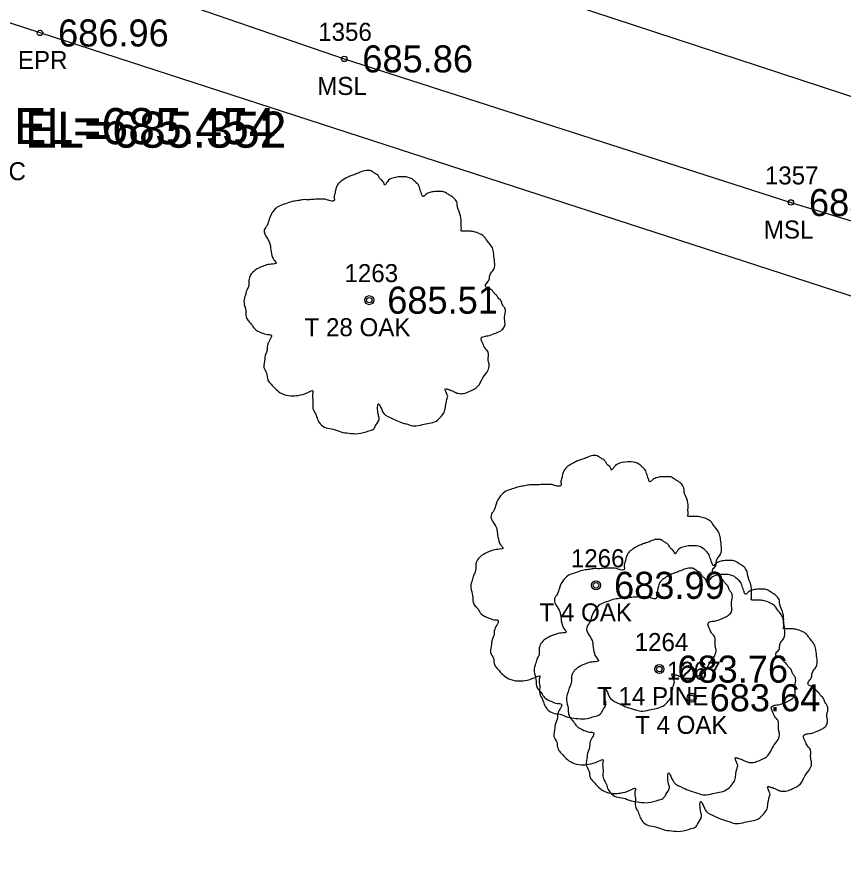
# Model space of a CAD drawing. Extents: x 1655137 to 1657928, y 1003994 to 1005407.
# Drawn here: x 1655939.35 to 1655985.18, y 1004711.37 to 1004758.76 of the extents above; entities that cross this region are included whole.
import ezdxf

# ---------------------------------------------------------------- set-up
doc = ezdxf.new("R2010")
doc.units = 0
for name, color, linetype in [('RD_EX_DR_Pipe_txCode', 7, 'Continuous'), ('RD_EX_Misc', 7, 'Continuous'), ('RD_EX_Misc_txCode', 7, 'Continuous'), ('RD_EX_Road', 7, 'Continuous'), ('RD_EX_Road_txCode', 7, 'Continuous'), ('RD_EX_TX_Misc_ELEV', 7, 'Continuous'), ('RD_EX_TX_Road_ELEV', 7, 'Continuous'), ('RD_EX_TX_VEG_ELEV', 7, 'Continuous'), ('RD_EX_VEG', 7, 'Continuous'), ('RD_EX_VEG_txCode', 7, 'Continuous'), ('RD_HC_Cl', 7, 'Continuous'), ('RD_SMD_Locator', 7, 'Continuous'), ('RD_TX_Pipe_ElevEX', 7, 'Continuous')]:
    doc.layers.add(name, color=color, linetype=linetype)

msp = doc.modelspace()

# ---------------------------------------------------------------- linework, layer by layer
at = {"layer": 'RD_EX_Misc'}
msp.add_lwpolyline([(1655875.572, 1004783.81), (1655899.124, 1004775.727), (1655924.143, 1004767.915), (1655957.486, 1004756.441), (1655982.243, 1004748.48), (1656011.779, 1004739.501), (1656033.158, 1004732.174), (1656057.837, 1004724.625), (1656091.047, 1004714.315), (1656106.296, 1004710.837), (1656119.065, 1004707.85), (1656127.527, 1004711.026), (1656137.413, 1004709.544), (1656150.275, 1004705.031), (1656164.334, 1004699.598), (1656171.578, 1004694.85), (1656180.966, 1004693.871), (1656197.975, 1004688.492), (1656215.111, 1004682.576), (1656240.683, 1004675.392), (1656271.878, 1004665.005), (1656304.44, 1004655.084)], dxfattribs=at)
at = {"layer": 'RD_EX_Road'}
msp.add_lwpolyline([(1656358.504, 1004619.827), (1656328.784, 1004629.475), (1656280.774, 1004645.393), (1656247.663, 1004656.111), (1656244.505, 1004656.516), (1656222.03, 1004663.569), (1656217.647, 1004665.963), (1656183.416, 1004677.324), (1656134.594, 1004693.716), (1656086.193, 1004709.749), (1656037.581, 1004726.126), (1655989.575, 1004741.988), (1655940.618, 1004757.879), (1655892.373, 1004773.61), (1655843.478, 1004789.356), (1655805.734, 1004801.404), (1655779.222, 1004810.434), (1655768.796, 1004813.103), (1655744.595, 1004822.13), (1655698.832, 1004837.654)], dxfattribs=at)
at = {"layer": 'RD_EX_VEG'}
for centre, radius in [((1655958.865, 1004743.064), 0.25), ((1655958.853, 1004743.046), 0.0001), ((1655971.438, 1004727.254), 0.25), ((1655971.425, 1004727.235), 0.0001), ((1655974.95, 1004722.609), 0.25), ((1655974.937, 1004722.59), 0.0001), ((1655976.737, 1004721.018), 0.25), ((1655976.724, 1004720.999), 0.0001)]:
    msp.add_circle(centre, radius, dxfattribs=at)
for points in [[(1655958.997, 1004750.232), (1655958.697, 1004750.257), (1655958.372, 1004750.157), (1655958.122, 1004750.057), (1655957.898, 1004749.982), (1655957.673, 1004749.882), (1655957.373, 1004749.707), (1655957.148, 1004749.507), (1655957.023, 1004749.257), (1655956.973, 1004749.032), (1655956.923, 1004748.757), (1655956.923, 1004748.582), (1655956.798, 1004748.557), (1655956.648, 1004748.582), (1655956.398, 1004748.657), (1655956.148, 1004748.657), (1655955.898, 1004748.657), (1655955.549, 1004748.632), (1655955.199, 1004748.632), (1655954.924, 1004748.582), (1655954.599, 1004748.532), (1655954.224, 1004748.407), (1655953.874, 1004748.282), (1655953.574, 1004748.033), (1655953.325, 1004747.558), (1655953.2, 1004747.208), (1655953.05, 1004746.958), (1655953.2, 1004746.508), (1655953.375, 1004746.158), (1655953.399, 1004745.958), (1655953.474, 1004745.534), (1655953.574, 1004745.309), (1655953.699, 1004745.109), (1655953.624, 1004745.084), (1655953.25, 1004745.034), (1655952.95, 1004744.934), (1655952.525, 1004744.709), (1655952.3, 1004744.484), (1655952.2, 1004744.159), (1655952.175, 1004743.809), (1655952.075, 1004743.61), (1655952, 1004743.335), (1655951.975, 1004743.26), (1655951.925, 1004742.935), (1655952.025, 1004742.485), (1655952.05, 1004742.135), (1655952.175, 1004741.91), (1655952.325, 1004741.735), (1655952.5, 1004741.485), (1655952.9, 1004741.261), (1655953.225, 1004741.161), (1655953.424, 1004741.136), (1655953.25, 1004740.636), (1655953.2, 1004740.286), (1655953.075, 1004739.886), (1655953.075, 1004739.811), (1655953.025, 1004739.336), (1655953.175, 1004739.011), (1655953.25, 1004738.637), (1655953.424, 1004738.412), (1655953.699, 1004738.112), (1655954.024, 1004737.887), (1655954.524, 1004737.762), (1655954.924, 1004737.787), (1655955.499, 1004737.962), (1655955.748, 1004738.037), (1655955.723, 1004737.862), (1655955.748, 1004737.487), (1655955.748, 1004737.062), (1655955.898, 1004736.738), (1655955.998, 1004736.463), (1655956.148, 1004736.213), (1655956.473, 1004735.988), (1655956.873, 1004735.913), (1655957.298, 1004735.763), (1655957.748, 1004735.688), (1655958.247, 1004735.663), (1655958.847, 1004735.813), (1655959.122, 1004735.938), (1655959.222, 1004736.113), (1655959.422, 1004736.488), (1655959.372, 1004736.713), (1655959.397, 1004737.312), (1655959.497, 1004737.137), (1655959.672, 1004736.787), (1655960.172, 1004736.488), (1655960.571, 1004736.313), (1655961.046, 1004736.163), (1655961.346, 1004736.088), (1655961.821, 1004736.163), (1655962.196, 1004736.238), (1655962.57, 1004736.363), (1655962.87, 1004736.638), (1655963.045, 1004736.912), (1655963.095, 1004737.187), (1655963.17, 1004737.562), (1655963.22, 1004737.737)], [(1655963.22, 1004737.737), (1655963.145, 1004737.912), (1655963.095, 1004738.162), (1655963.17, 1004738.137), (1655963.345, 1004738.087), (1655963.62, 1004737.962), (1655963.845, 1004737.887), (1655964.17, 1004737.912), (1655964.445, 1004738.012), (1655964.894, 1004738.287), (1655965.169, 1004738.762), (1655965.444, 1004739.161), (1655965.519, 1004739.486), (1655965.469, 1004739.711), (1655965.444, 1004740.211), (1655965.244, 1004740.461), (1655965.194, 1004740.586), (1655965.094, 1004740.986), (1655965.169, 1004741.036), (1655965.444, 1004741.086), (1655965.819, 1004741.211), (1655966.094, 1004741.335), (1655966.319, 1004741.51), (1655966.394, 1004741.735), (1655966.369, 1004742.135), (1655966.419, 1004742.535), (1655966.344, 1004742.685), (1655966.244, 1004742.835), (1655966.169, 1004743.035), (1655966.019, 1004743.185), (1655965.919, 1004743.335), (1655965.819, 1004743.435), (1655965.694, 1004743.585), (1655965.519, 1004743.709), (1655965.369, 1004743.759), (1655965.319, 1004743.909), (1655965.469, 1004744.109), (1655965.519, 1004744.209), (1655965.544, 1004744.434), (1655965.769, 1004744.784), (1655965.819, 1004745.184), (1655965.769, 1004745.609), (1655965.719, 1004745.884), (1655965.569, 1004746.158), (1655965.369, 1004746.408), (1655965.244, 1004746.583), (1655965.069, 1004746.708), (1655964.745, 1004746.833), (1655964.495, 1004746.883), (1655964.145, 1004746.883), (1655963.945, 1004746.933), (1655963.97, 1004746.983), (1655963.97, 1004747.133), (1655963.97, 1004747.408), (1655963.895, 1004747.858), (1655963.745, 1004748.357), (1655963.745, 1004748.382), (1655963.645, 1004748.632), (1655963.42, 1004748.832), (1655963.245, 1004748.932), (1655963.045, 1004749.057), (1655962.795, 1004749.082), (1655962.496, 1004749.082), (1655962.221, 1004749.032), (1655962.021, 1004748.932), (1655961.846, 1004748.807), (1655961.771, 1004748.957), (1655961.671, 1004749.257), (1655961.621, 1004749.407), (1655961.471, 1004749.582), (1655961.246, 1004749.782), (1655960.796, 1004749.907), (1655960.172, 1004749.832), (1655959.872, 1004749.632), (1655959.722, 1004749.457), (1655959.672, 1004749.582), (1655959.472, 1004749.782), (1655959.372, 1004749.957), (1655959.197, 1004750.082), (1655959.047, 1004750.182), (1655958.947, 1004750.232)], [(1655971.57, 1004734.421), (1655971.27, 1004734.446), (1655970.945, 1004734.346), (1655970.695, 1004734.246), (1655970.47, 1004734.171), (1655970.245, 1004734.071), (1655969.945, 1004733.897), (1655969.721, 1004733.697), (1655969.596, 1004733.447), (1655969.546, 1004733.222), (1655969.496, 1004732.947), (1655969.496, 1004732.772), (1655969.371, 1004732.747), (1655969.221, 1004732.772), (1655968.971, 1004732.847), (1655968.721, 1004732.847), (1655968.471, 1004732.847), (1655968.121, 1004732.822), (1655967.771, 1004732.822), (1655967.497, 1004732.772), (1655967.172, 1004732.722), (1655966.797, 1004732.597), (1655966.447, 1004732.472), (1655966.147, 1004732.222), (1655965.897, 1004731.748), (1655965.772, 1004731.398), (1655965.622, 1004731.148), (1655965.772, 1004730.698), (1655965.947, 1004730.348), (1655965.972, 1004730.148), (1655966.047, 1004729.723), (1655966.147, 1004729.499), (1655966.272, 1004729.299), (1655966.197, 1004729.274), (1655965.822, 1004729.224), (1655965.522, 1004729.124), (1655965.098, 1004728.899), (1655964.873, 1004728.674), (1655964.773, 1004728.349), (1655964.748, 1004727.999), (1655964.648, 1004727.799), (1655964.573, 1004727.524), (1655964.548, 1004727.449), (1655964.498, 1004727.125), (1655964.598, 1004726.675), (1655964.623, 1004726.325), (1655964.748, 1004726.1), (1655964.898, 1004725.925), (1655965.073, 1004725.675), (1655965.472, 1004725.45), (1655965.797, 1004725.35), (1655965.997, 1004725.325), (1655965.822, 1004724.826), (1655965.772, 1004724.476), (1655965.647, 1004724.076), (1655965.647, 1004724.001), (1655965.597, 1004723.526), (1655965.747, 1004723.201), (1655965.822, 1004722.826), (1655965.997, 1004722.602), (1655966.272, 1004722.302), (1655966.597, 1004722.077), (1655967.097, 1004721.952), (1655967.497, 1004721.977), (1655968.071, 1004722.152), (1655968.321, 1004722.227), (1655968.296, 1004722.052), (1655968.321, 1004721.677), (1655968.321, 1004721.252), (1655968.471, 1004720.927), (1655968.571, 1004720.652), (1655968.721, 1004720.402), (1655969.046, 1004720.178), (1655969.446, 1004720.103), (1655969.87, 1004719.953), (1655970.32, 1004719.878), (1655970.82, 1004719.853), (1655971.42, 1004720.003), (1655971.695, 1004720.128), (1655971.795, 1004720.303), (1655971.995, 1004720.677), (1655971.945, 1004720.902), (1655971.97, 1004721.502), (1655972.069, 1004721.327), (1655972.244, 1004720.977), (1655972.744, 1004720.677), (1655973.144, 1004720.502), (1655973.619, 1004720.352), (1655973.919, 1004720.278), (1655974.393, 1004720.352), (1655974.768, 1004720.427), (1655975.143, 1004720.552), (1655975.443, 1004720.827), (1655975.618, 1004721.102), (1655975.668, 1004721.377), (1655975.743, 1004721.752), (1655975.793, 1004721.927)], [(1655975.793, 1004721.927), (1655975.718, 1004722.102), (1655975.668, 1004722.352), (1655975.743, 1004722.327), (1655975.918, 1004722.277), (1655976.193, 1004722.152), (1655976.418, 1004722.077), (1655976.742, 1004722.102), (1655977.017, 1004722.202), (1655977.467, 1004722.477), (1655977.742, 1004722.951), (1655978.017, 1004723.351), (1655978.092, 1004723.676), (1655978.042, 1004723.901), (1655978.017, 1004724.401), (1655977.817, 1004724.651), (1655977.767, 1004724.776), (1655977.667, 1004725.175), (1655977.742, 1004725.225), (1655978.017, 1004725.275), (1655978.392, 1004725.4), (1655978.667, 1004725.525), (1655978.892, 1004725.7), (1655978.966, 1004725.925), (1655978.942, 1004726.325), (1655978.991, 1004726.725), (1655978.917, 1004726.875), (1655978.817, 1004727.025), (1655978.742, 1004727.225), (1655978.592, 1004727.374), (1655978.492, 1004727.524), (1655978.392, 1004727.624), (1655978.267, 1004727.774), (1655978.092, 1004727.899), (1655977.942, 1004727.949), (1655977.892, 1004728.099), (1655978.042, 1004728.299), (1655978.092, 1004728.399), (1655978.117, 1004728.624), (1655978.342, 1004728.974), (1655978.392, 1004729.374), (1655978.342, 1004729.798), (1655978.292, 1004730.073), (1655978.142, 1004730.348), (1655977.942, 1004730.598), (1655977.817, 1004730.773), (1655977.642, 1004730.898), (1655977.317, 1004731.023), (1655977.067, 1004731.073), (1655976.717, 1004731.073), (1655976.518, 1004731.123), (1655976.543, 1004731.173), (1655976.543, 1004731.323), (1655976.543, 1004731.598), (1655976.468, 1004732.047), (1655976.318, 1004732.547), (1655976.318, 1004732.572), (1655976.218, 1004732.822), (1655975.993, 1004733.022), (1655975.818, 1004733.122), (1655975.618, 1004733.247), (1655975.368, 1004733.272), (1655975.068, 1004733.272), (1655974.793, 1004733.222), (1655974.593, 1004733.122), (1655974.418, 1004732.997), (1655974.343, 1004733.147), (1655974.244, 1004733.447), (1655974.194, 1004733.597), (1655974.044, 1004733.772), (1655973.819, 1004733.972), (1655973.369, 1004734.096), (1655972.744, 1004734.022), (1655972.444, 1004733.822), (1655972.294, 1004733.647), (1655972.244, 1004733.772), (1655972.044, 1004733.972), (1655971.945, 1004734.146), (1655971.77, 1004734.271), (1655971.62, 1004734.371), (1655971.52, 1004734.421)], [(1655975.082, 1004729.776), (1655974.782, 1004729.801), (1655974.457, 1004729.701), (1655974.207, 1004729.601), (1655973.982, 1004729.526), (1655973.757, 1004729.426), (1655973.458, 1004729.252), (1655973.233, 1004729.052), (1655973.108, 1004728.802), (1655973.058, 1004728.577), (1655973.008, 1004728.302), (1655973.008, 1004728.127), (1655972.883, 1004728.102), (1655972.733, 1004728.127), (1655972.483, 1004728.202), (1655972.233, 1004728.202), (1655971.983, 1004728.202), (1655971.633, 1004728.177), (1655971.283, 1004728.177), (1655971.009, 1004728.127), (1655970.684, 1004728.077), (1655970.309, 1004727.952), (1655969.959, 1004727.827), (1655969.659, 1004727.577), (1655969.409, 1004727.102), (1655969.284, 1004726.753), (1655969.134, 1004726.503), (1655969.284, 1004726.053), (1655969.459, 1004725.703), (1655969.484, 1004725.503), (1655969.559, 1004725.078), (1655969.659, 1004724.853), (1655969.784, 1004724.653), (1655969.709, 1004724.629), (1655969.334, 1004724.579), (1655969.034, 1004724.479), (1655968.61, 1004724.254), (1655968.385, 1004724.029), (1655968.285, 1004723.704), (1655968.26, 1004723.354), (1655968.16, 1004723.154), (1655968.085, 1004722.879), (1655968.06, 1004722.804), (1655968.01, 1004722.479), (1655968.11, 1004722.03), (1655968.135, 1004721.68), (1655968.26, 1004721.455), (1655968.41, 1004721.28), (1655968.585, 1004721.03), (1655968.984, 1004720.805), (1655969.309, 1004720.705), (1655969.509, 1004720.68), (1655969.334, 1004720.18), (1655969.284, 1004719.831), (1655969.159, 1004719.431), (1655969.159, 1004719.356), (1655969.109, 1004718.881), (1655969.259, 1004718.556), (1655969.334, 1004718.181), (1655969.509, 1004717.956), (1655969.784, 1004717.657), (1655970.109, 1004717.432), (1655970.609, 1004717.307), (1655971.009, 1004717.332), (1655971.583, 1004717.507), (1655971.833, 1004717.582), (1655971.808, 1004717.407), (1655971.833, 1004717.032), (1655971.833, 1004716.607), (1655971.983, 1004716.282), (1655972.083, 1004716.007), (1655972.233, 1004715.757), (1655972.558, 1004715.533), (1655972.958, 1004715.458), (1655973.383, 1004715.308), (1655973.832, 1004715.233), (1655974.332, 1004715.208), (1655974.932, 1004715.358), (1655975.207, 1004715.483), (1655975.307, 1004715.657), (1655975.507, 1004716.032), (1655975.457, 1004716.257), (1655975.482, 1004716.857), (1655975.582, 1004716.682), (1655975.757, 1004716.332), (1655976.256, 1004716.032), (1655976.656, 1004715.857), (1655977.131, 1004715.707), (1655977.431, 1004715.632), (1655977.906, 1004715.707), (1655978.28, 1004715.782), (1655978.655, 1004715.907), (1655978.955, 1004716.182), (1655979.13, 1004716.457), (1655979.18, 1004716.732), (1655979.255, 1004717.107), (1655979.305, 1004717.282)], [(1655979.305, 1004717.282), (1655979.23, 1004717.457), (1655979.18, 1004717.707), (1655979.255, 1004717.682), (1655979.43, 1004717.632), (1655979.705, 1004717.507), (1655979.93, 1004717.432), (1655980.255, 1004717.457), (1655980.529, 1004717.557), (1655980.979, 1004717.832), (1655981.254, 1004718.306), (1655981.529, 1004718.706), (1655981.604, 1004719.031), (1655981.554, 1004719.256), (1655981.529, 1004719.756), (1655981.329, 1004720.006), (1655981.279, 1004720.13), (1655981.179, 1004720.53), (1655981.254, 1004720.58), (1655981.529, 1004720.63), (1655981.904, 1004720.755), (1655982.179, 1004720.88), (1655982.404, 1004721.055), (1655982.479, 1004721.28), (1655982.454, 1004721.68), (1655982.504, 1004722.08), (1655982.429, 1004722.23), (1655982.329, 1004722.379), (1655982.254, 1004722.579), (1655982.104, 1004722.729), (1655982.004, 1004722.879), (1655981.904, 1004722.979), (1655981.779, 1004723.129), (1655981.604, 1004723.254), (1655981.454, 1004723.304), (1655981.404, 1004723.454), (1655981.554, 1004723.654), (1655981.604, 1004723.754), (1655981.629, 1004723.979), (1655981.854, 1004724.329), (1655981.904, 1004724.728), (1655981.854, 1004725.153), (1655981.804, 1004725.428), (1655981.654, 1004725.703), (1655981.454, 1004725.953), (1655981.329, 1004726.128), (1655981.154, 1004726.253), (1655980.829, 1004726.378), (1655980.579, 1004726.428), (1655980.23, 1004726.428), (1655980.03, 1004726.478), (1655980.055, 1004726.528), (1655980.055, 1004726.678), (1655980.055, 1004726.953), (1655979.98, 1004727.402), (1655979.83, 1004727.902), (1655979.83, 1004727.927), (1655979.73, 1004728.177), (1655979.505, 1004728.377), (1655979.33, 1004728.477), (1655979.13, 1004728.602), (1655978.88, 1004728.627), (1655978.58, 1004728.627), (1655978.305, 1004728.577), (1655978.105, 1004728.477), (1655977.931, 1004728.352), (1655977.856, 1004728.502), (1655977.756, 1004728.802), (1655977.706, 1004728.952), (1655977.556, 1004729.127), (1655977.331, 1004729.326), (1655976.881, 1004729.451), (1655976.256, 1004729.376), (1655975.956, 1004729.177), (1655975.806, 1004729.002), (1655975.757, 1004729.127), (1655975.557, 1004729.326), (1655975.457, 1004729.501), (1655975.282, 1004729.626), (1655975.132, 1004729.726), (1655975.032, 1004729.776)], [(1655976.869, 1004728.185), (1655976.569, 1004728.21), (1655976.244, 1004728.11), (1655975.994, 1004728.01), (1655975.769, 1004727.935), (1655975.544, 1004727.835), (1655975.245, 1004727.66), (1655975.02, 1004727.46), (1655974.895, 1004727.21), (1655974.845, 1004726.985), (1655974.795, 1004726.71), (1655974.795, 1004726.535), (1655974.67, 1004726.51), (1655974.52, 1004726.535), (1655974.27, 1004726.61), (1655974.02, 1004726.61), (1655973.77, 1004726.61), (1655973.42, 1004726.585), (1655973.07, 1004726.585), (1655972.796, 1004726.535), (1655972.471, 1004726.486), (1655972.096, 1004726.361), (1655971.746, 1004726.236), (1655971.446, 1004725.986), (1655971.196, 1004725.511), (1655971.071, 1004725.161), (1655970.921, 1004724.911), (1655971.071, 1004724.461), (1655971.246, 1004724.112), (1655971.271, 1004723.912), (1655971.346, 1004723.487), (1655971.446, 1004723.262), (1655971.571, 1004723.062), (1655971.496, 1004723.037), (1655971.121, 1004722.987), (1655970.821, 1004722.887), (1655970.397, 1004722.662), (1655970.172, 1004722.437), (1655970.072, 1004722.112), (1655970.047, 1004721.763), (1655969.947, 1004721.563), (1655969.872, 1004721.288), (1655969.847, 1004721.213), (1655969.797, 1004720.888), (1655969.897, 1004720.438), (1655969.922, 1004720.088), (1655970.047, 1004719.863), (1655970.197, 1004719.689), (1655970.372, 1004719.439), (1655970.771, 1004719.214), (1655971.096, 1004719.114), (1655971.296, 1004719.089), (1655971.121, 1004718.589), (1655971.071, 1004718.239), (1655970.946, 1004717.839), (1655970.946, 1004717.764), (1655970.896, 1004717.29), (1655971.046, 1004716.965), (1655971.121, 1004716.59), (1655971.296, 1004716.365), (1655971.571, 1004716.065), (1655971.896, 1004715.84), (1655972.396, 1004715.715), (1655972.796, 1004715.74), (1655973.37, 1004715.915), (1655973.62, 1004715.99), (1655973.595, 1004715.815), (1655973.62, 1004715.44), (1655973.62, 1004715.016), (1655973.77, 1004714.691), (1655973.87, 1004714.416), (1655974.02, 1004714.166), (1655974.345, 1004713.941), (1655974.745, 1004713.866), (1655975.17, 1004713.716), (1655975.619, 1004713.641), (1655976.119, 1004713.616), (1655976.719, 1004713.766), (1655976.994, 1004713.891), (1655977.094, 1004714.066), (1655977.294, 1004714.441), (1655977.244, 1004714.666), (1655977.269, 1004715.265), (1655977.369, 1004715.09), (1655977.544, 1004714.741), (1655978.043, 1004714.441), (1655978.443, 1004714.266), (1655978.918, 1004714.116), (1655979.218, 1004714.041), (1655979.693, 1004714.116), (1655980.067, 1004714.191), (1655980.442, 1004714.316), (1655980.742, 1004714.591), (1655980.917, 1004714.866), (1655980.967, 1004715.14), (1655981.042, 1004715.515), (1655981.092, 1004715.69)], [(1655981.092, 1004715.69), (1655981.017, 1004715.865), (1655980.967, 1004716.115), (1655981.042, 1004716.09), (1655981.217, 1004716.04), (1655981.492, 1004715.915), (1655981.717, 1004715.84), (1655982.042, 1004715.865), (1655982.316, 1004715.965), (1655982.766, 1004716.24), (1655983.041, 1004716.715), (1655983.316, 1004717.115), (1655983.391, 1004717.439), (1655983.341, 1004717.664), (1655983.316, 1004718.164), (1655983.116, 1004718.414), (1655983.066, 1004718.539), (1655982.966, 1004718.939), (1655983.041, 1004718.989), (1655983.316, 1004719.039), (1655983.691, 1004719.164), (1655983.966, 1004719.289), (1655984.191, 1004719.464), (1655984.266, 1004719.689), (1655984.241, 1004720.088), (1655984.291, 1004720.488), (1655984.216, 1004720.638), (1655984.116, 1004720.788), (1655984.041, 1004720.988), (1655983.891, 1004721.138), (1655983.791, 1004721.288), (1655983.691, 1004721.388), (1655983.566, 1004721.538), (1655983.391, 1004721.663), (1655983.241, 1004721.713), (1655983.191, 1004721.863), (1655983.341, 1004722.062), (1655983.391, 1004722.162), (1655983.416, 1004722.387), (1655983.641, 1004722.737), (1655983.691, 1004723.137), (1655983.641, 1004723.562), (1655983.591, 1004723.837), (1655983.441, 1004724.112), (1655983.241, 1004724.361), (1655983.116, 1004724.536), (1655982.941, 1004724.661), (1655982.616, 1004724.786), (1655982.366, 1004724.836), (1655982.017, 1004724.836), (1655981.817, 1004724.886), (1655981.842, 1004724.936), (1655981.842, 1004725.086), (1655981.842, 1004725.361), (1655981.767, 1004725.811), (1655981.617, 1004726.311), (1655981.617, 1004726.336), (1655981.517, 1004726.585), (1655981.292, 1004726.785), (1655981.117, 1004726.885), (1655980.917, 1004727.01), (1655980.667, 1004727.035), (1655980.367, 1004727.035), (1655980.092, 1004726.985), (1655979.892, 1004726.885), (1655979.718, 1004726.76), (1655979.643, 1004726.91), (1655979.543, 1004727.21), (1655979.493, 1004727.36), (1655979.343, 1004727.535), (1655979.118, 1004727.735), (1655978.668, 1004727.86), (1655978.043, 1004727.785), (1655977.743, 1004727.585), (1655977.593, 1004727.41), (1655977.544, 1004727.535), (1655977.344, 1004727.735), (1655977.244, 1004727.91), (1655977.069, 1004728.035), (1655976.919, 1004728.135), (1655976.819, 1004728.185)]]:
    msp.add_spline(points, degree=3, dxfattribs=at)
at = {"layer": 'RD_HC_Cl'}
msp.add_line((1655701.505, 1004847.777), (1656069.258, 1004726.842), dxfattribs=at)
at = {"layer": 'RD_SMD_Locator'}
for centre in [(1655940.618, 1004757.879), (1655957.486, 1004756.441), (1655982.243, 1004748.48), (1655958.865, 1004743.064), (1655971.438, 1004727.254), (1655974.95, 1004722.609), (1655976.737, 1004721.018)]:
    msp.add_circle(centre, 0.15, dxfattribs=at)

# ---------------------------------------------------------------- texts
at = {"layer": 'RD_EX_DR_Pipe_txCode'}
msp.add_text('PA 15 RC', height=1, dxfattribs=at).set_placement((1655933.891, 1004749.714))
at = {"layer": 'RD_EX_Misc_txCode'}
for s, p in [('1356', (1655956.037, 1004757.441)), ('MSL', (1655955.984, 1004754.441)), ('1357', (1655980.798, 1004749.48)), ('MSL', (1655980.741, 1004746.48))]:
    msp.add_text(s, height=1, dxfattribs=at).set_placement(p)
at = {"layer": 'RD_EX_Road_txCode'}
msp.add_text('EPR', height=1, dxfattribs=at).set_placement((1655939.389, 1004755.879))
at = {"layer": 'RD_EX_TX_Misc_ELEV'}
for s, p in [('685.86', (1655958.486, 1004755.691)), ('683.87', (1655983.243, 1004747.73))]:
    msp.add_text(s, height=1.5, dxfattribs=at).set_placement(p)
at = {"layer": 'RD_EX_TX_Road_ELEV'}
msp.add_text('686.96', height=1.5, dxfattribs=at).set_placement((1655941.618, 1004757.129))
at = {"layer": 'RD_EX_TX_VEG_ELEV'}
for s, p in [('685.51', (1655959.865, 1004742.314)), ('683.99', (1655972.438, 1004726.504)), ('683.76', (1655975.95, 1004721.859)), ('683.64', (1655977.737, 1004720.268))]:
    msp.add_text(s, height=1.5, dxfattribs=at).set_placement(p)
at = {"layer": 'RD_EX_VEG_txCode'}
for s, p in [('1263', (1655957.495, 1004744.064)), ('T 28 OAK', (1655955.282, 1004741.064)), ('1266', (1655970.044, 1004728.254)), ('T 4 OAK', (1655968.304, 1004725.254)), ('1264', (1655973.58, 1004723.609)), ('1267', (1655975.367, 1004722.018)), ('T 14 PINE', (1655971.497, 1004720.609)), ('T 4 OAK', (1655973.603, 1004719.018))]:
    msp.add_text(s, height=1, dxfattribs=at).set_placement(p)
at = {"layer": 'RD_TX_Pipe_ElevEX'}
for s, p in [('EL=685.454', (1655939.182, 1004751.714)), ('EL=685.352', (1655939.783, 1004751.518))]:
    msp.add_text(s, height=2, dxfattribs=at).set_placement(p)

doc.saveas('drawing.dxf')
